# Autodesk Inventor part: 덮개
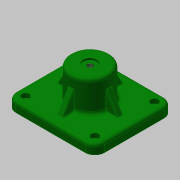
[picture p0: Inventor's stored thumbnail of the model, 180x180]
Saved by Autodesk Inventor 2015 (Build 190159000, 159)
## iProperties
Created: 2017-08
Part Number: 덮개
Material: 알루미늄 6061
Document SubType Name: Modeling
Designer: mduedu
Density: 1 g/cm^3
Appearance: 진녹색
Author: mduedu
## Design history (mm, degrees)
sketch "스케치1"
  geometry: L1 (46, -41)-(-46, -41); L2 (-46, -41)-(-46, 41); L3 (-46, 41)-(46, 41); L4 (46, 41)-(46, -41); 1 further point
  constraints: 8 end point, 2 parallel, 1 horizontal, 1 perpendicular
  dimensions: "d0" = 92 distance of L2.end L3.end; "d2" = 82 distance of L1.end L2.end; "d3" = 41 distance from line of L3 point (0, 0) (= 0.5 x d2); "d4" = 46 distance from line of point (0, 0) L4 (= 0.5 x d0)
extrude "돌출1" new body sketch "스케치1" distance "d5" = 10; taper "d6" = 0 deg
sketch "스케치2"
  geometry: C1 r 20 at (0, 0); 1 further point
  constraints: 1 centre point, 1 coincident
  dimensions: "d55" = 40 diameter of C1
extrude "돌출2" join sketch "스케치2" distance "d9" = 32; taper "d10" = 0 deg
sketch "스케치3"
  geometry: L1 (-26, -26)-(26, -26); L2 (26, -26)-(26, 26); L3 (26, 26)-(-26, 26); L4 (-26, 26)-(-26, -26); L5 (-26, -26)-(26, 26); L6 (26, -26)-(-26, 26); 1 further point
  constraints: 12 end point, 2 midpoint, 2 parallel, 2 perpendicular, 1 horizontal
  dimensions: "d11" = 52 distance of L3.end L2.end
extrude "돌출3" join sketch "스케치3" distance "d12" = 6; taper "d13" = 0 deg
sketch "스케치4"
  geometry: L1 (-17, -17)-(17, -17); L2 (17, -17)-(17, 17); L3 (17, 17)-(-17, 17); L4 (-17, 17)-(-17, -17); L5 (-17, -17)-(17, 17); L6 (17, -17)-(-17, 17); 1 further point
  constraints: 12 end point, 2 midpoint, 2 parallel, 2 perpendicular, 1 horizontal
  dimensions: "d14" = 34 distance of L2.end L3.end
extrude "돌출4" cut sketch "스케치4" distance "d16" = 5; taper "d17" = 0 deg
sketch "스케치5"
  geometry: C1 r 9 at (0, 0); 1 further point
  constraints: 1 centre point, 1 coincident
  dimensions: "d18" = 18 diameter of C1
extrude "돌출5" cut sketch "스케치5" distance "d19" = 34; taper "d20" = 0 deg
sketch "스케치6"
  geometry: 2 further points
  constraints: 1 coincident
hole "구멍1" sketch "스케치6" at (0, 0) diameter "d21" = 5.917; stored, may be unused: countersink angle "d25" = 90 deg, drill point angle "d27" = 118 deg; dims "d22" = 6, "d23" = 14, "d24" = 2, "d26" = 8
fillet "모깎기1" dims "d36" = 10
fillet "모깎기3" dims "d38" = 3
fillet "모깎기4" dims "d39" = 3
fillet "모깎기5" dims "d40" = 3
chamfer "모따기1" distance "d41" = 1; stored, may be unused: second distance "d42" = 2, angle "d43" = 45 deg
fillet "모깎기6" dims "d44" = 3
fillet "모깎기7" dims "d45" = 3
fillet "모깎기8" dims "d46" = 3
sketch "스케치8"
  geometry: A1 r 10 centre (-36, -31) between (-46, -31) and (-36, -41) reference; A2 r 10 centre (-36, 31) between (-36, 41) and (-46, 31) reference; A3 r 10 centre (36, 31) between (46, 31) and (36, 41) reference; A4 r 10 centre (36, -31) between (36, -41) and (46, -31) reference; 5 further points
  constraints: 4 coincident
sketch "스케치9"
  geometry: 4 further points
  constraints: 4 other
hole "구멍3" sketch "스케치9" at (-36, -31), (-36, 31), (36, 31), (36, -31) diameter "d48" = 4.5; stored, may be unused: countersink angle "d52" = 90 deg, drill point angle "d54" = 0 deg; dims "d49" = 6, "d50" = 8, "d51" = 4.6, "d53" = 8
sketch "스케치10"
  geometry: L1 (-7, 40)-(-2.958, 40) reference; L2 (-2.958, 40)-(-2.958, 33) reference; L3 (-2.958, 33)-(-6, 33) reference; L4 (-9, 30)-(-9, -1) reference; L5 (-9, -1)-(-14, -1) reference; L6 (-17, -4)-(-17, -6) reference; L7 (-17, -6)-(-25, -6) reference; L8 (-25, -6)-(-26, -5) reference; L9 (-26, -5)-(-26, 0) reference; L10 (-26, 0)-(-46, 0) reference; L11 (-46, 0)-(-46, 7) reference; L12 (-43, 10)-(-23, 10) reference; L13 (-20, 13)-(-20, 39) reference; L14 (-17, 42)-(-7, 42) reference; L15 (-7, 42)-(-7, 40) reference; L16 (2.958, 40)-(7, 40) reference; L17 (7, 40)-(7, 42) reference; L18 (7, 42)-(17, 42) reference; L19 (20, 39)-(20, 13) reference; L20 (23, 10)-(43, 10) reference; L21 (46, 7)-(46, 0) reference; L22 (46, 0)-(26, 0) reference; L23 (26, 0)-(26, -5) reference; L24 (26, -5)-(25, -6) reference; L25 (25, -6)-(17, -6) reference; L26 (17, -6)-(17, -4) reference; L27 (14, -1)-(9, -1) reference; L28 (9, -1)-(9, 30) reference; L29 (6, 33)-(2.958, 33) reference; L30 (2.958, 33)-(2.958, 40) reference; L31 (31.547, 10)-(20, 30); A1 r 3 centre (-6, 30) between (-6, 33) and (-9, 30) reference; A2 r 3 centre (-14, -4) between (-14, -1) and (-17, -4) reference; A3 r 3 centre (-43, 7) between (-43, 10) and (-46, 7) reference; A4 r 3 centre (-23, 13) between (-23, 10) and (-20, 13) reference; A5 r 3 centre (-17, 39) between (-17, 42) and (-20, 39) reference; A6 r 3 centre (17, 39) between (20, 39) and (17, 42) reference; A7 r 3 centre (23, 13) between (20, 13) and (23, 10) reference; A8 r 3 centre (43, 7) between (46, 7) and (43, 10) reference; A9 r 3 centre (14, -4) between (17, -4) and (14, -1) reference; A10 r 3 centre (6, 30) between (9, 30) and (6, 33) reference; 1 further point
  constraints: 2 end point, 2 point on line
  dimensions: "d56" = 20 distance from line of L31.end L20; "d57" = 120 deg angle of L31 L20
feature "리브1" sketch "스케치10" dims "d58" = 1, "d59" = 6, "d60" = 0, "d61" = 0, "d62" = 1, "d63" = 1
fillet "모깎기9" dims "d64" = 1
fillet "모깎기10" dims "d65" = 1
node "솔리드1"
pattern_circular "원형 패턴1" dims "d67" = 360 deg
node "절단 모서리 투영1"
